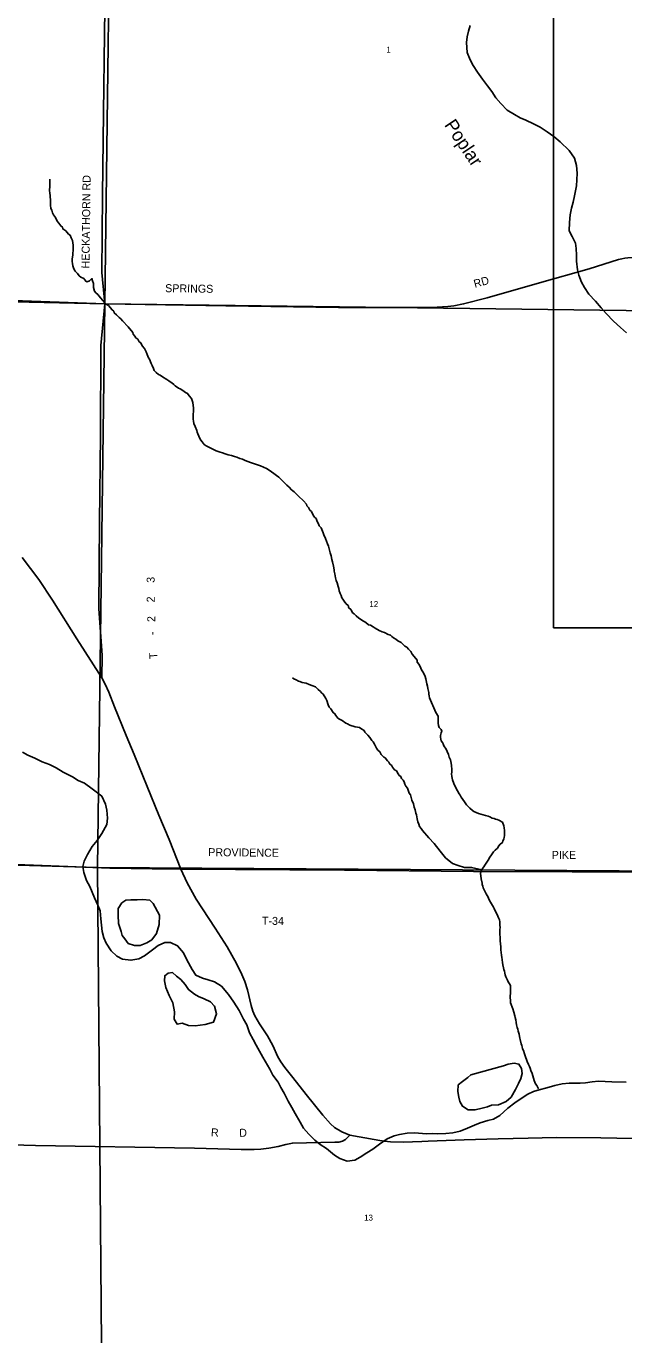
# Model space of a CAD drawing. Extents: x 1312308 to 1684953, y 460642 to 865172.
# Drawn here: x 1437978 to 1443580, y 657978 to 670241 of the extents above; entities that cross this region are included whole.
import ezdxf

# ---------------------------------------------------------------- set-up
doc = ezdxf.new("R2010")
doc.units = 0
for name, color, linetype in [('GM_X_County_Road', 7, 'Continuous'), ('GM_X_County_Road_Text', 7, 'Continuous'), ('GM_X_Minor_Lake', 7, 'Continuous'), ('GM_X_Minor_River', 7, 'Continuous'), ('GM_X_Minor_River_Text', 7, 'Continuous'), ('GM_X_Section', 7, 'Continuous'), ('GM_X_Section_Text', 7, 'Continuous'), ('GM_X_Township_Road', 7, 'Continuous'), ('GM_X_Township_Road_Text', 7, 'Continuous'), ('SH_Data', 7, 'Continuous')]:
    doc.layers.add(name, color=color, linetype=linetype)

msp = doc.modelspace()

# ---------------------------------------------------------------- linework, layer by layer
at = {"layer": 'GM_X_County_Road'}
for points in [[(1436235, 667699), (1437294, 667672), (1438715, 667638), (1439848, 667622), (1440906, 667606), (1441732, 667606), (1441830, 667608), (1441930, 667615), (1441987, 667622), (1442078, 667638), (1442298, 667695), (1442788, 667837), (1443254, 667967), (1443529, 668054), (1443561, 668061), (1443588, 668067), (1443617, 668070), (1444097, 668076)], [(1437941, 665263), (1438098, 665055), (1438226, 664863), (1438453, 664500), (1438688, 664134), (1438718, 664077), (1438753, 664001), (1438805, 663862), (1438914, 663594), (1438991, 663417), (1439111, 663118), (1439221, 662847), (1439318, 662619), (1439428, 662343), (1439486, 662214), (1439571, 662061), (1439748, 661789), (1439863, 661615), (1439949, 661458), (1440000, 661354), (1440026, 661290), (1440052, 661211), (1440086, 661063), (1440102, 661012), (1440122, 660968), (1440164, 660894), (1440240, 660779), (1440289, 660690), (1440338, 660584), (1440364, 660538), (1440401, 660484), (1440476, 660391), (1440603, 660231), (1440759, 660037), (1440831, 659955), (1440869, 659922), (1440936, 659882), (1441011, 659850), (1441100, 659834), (1441293, 659800), (1441338, 659793), (1441393, 659787), (1441510, 659784), (1441686, 659790), (1441745, 659793), (1442084, 659805), (1442401, 659816), (1442684, 659822), (1442945, 659827), (1443364, 659823), (1443962, 659813)], [(1428093, 662563), (1428093, 662563), (1436008, 662458), (1438209, 662374), (1438762, 662352), (1439160, 662345), (1439428, 662343)]]:
    msp.add_lwpolyline(points, dxfattribs=at)
at = {"layer": 'GM_X_Minor_Lake'}
for points in [[(1439169, 662020), (1439136, 662053), (1439070, 662058), (1439019, 662055), (1438959, 662055), (1438911, 662050), (1438876, 662026), (1438841, 661973), (1438839, 661911), (1438844, 661832), (1438868, 661759), (1438879, 661719)], [(1438879, 661719), (1438903, 661690), (1438934, 661645), (1438992, 661628), (1439046, 661627), (1439109, 661652), (1439156, 661681), (1439199, 661740), (1439223, 661824), (1439227, 661910), (1439169, 662020)], [(1439349, 661373), (1439309, 661366), (1439276, 661343), (1439273, 661295), (1439286, 661234), (1439319, 661157), (1439353, 661090), (1439369, 661005), (1439366, 660935), (1439393, 660890), (1439441, 660899), (1439499, 660876), (1439563, 660875), (1439654, 660885), (1439733, 660907), (1439762, 660987), (1439742, 661057), (1439705, 661100), (1439645, 661126), (1439593, 661149), (1439556, 661172)], [(1439556, 661172), (1439498, 661213), (1439469, 661262), (1439428, 661307), (1439387, 661338), (1439349, 661373)], [(1442340, 660131), (1442406, 660134), (1442477, 660165), (1442524, 660206), (1442565, 660278), (1442592, 660335), (1442615, 660381), (1442626, 660427), (1442621, 660473), (1442596, 660516), (1442552, 660523), (1442496, 660516), (1442451, 660499), (1442145, 660414)], [(1442145, 660414), (1442118, 660391), (1442104, 660379), (1442067, 660351), (1442027, 660320), (1442023, 660260), (1442034, 660205), (1442044, 660165), (1442069, 660120), (1442122, 660087), (1442186, 660088), (1442253, 660103), (1442303, 660116), (1442340, 660131)]]:
    msp.add_lwpolyline(points, dxfattribs=at)
at = {"layer": 'GM_X_Minor_River'}
for points in [[(1443606, 667367), (1443549, 667419), (1443484, 667478), (1443413, 667550), (1443368, 667601), (1443313, 667663), (1443253, 667730), (1443212, 667793), (1443183, 667844), (1443158, 667907), (1443145, 667958), (1443136, 668038), (1443136, 668095), (1443133, 668159), (1443126, 668209), (1443095, 668270), (1443066, 668323), (1443070, 668402), (1443077, 668472), (1443090, 668536), (1443104, 668592), (1443117, 668652), (1443135, 668744), (1443140, 668800), (1443141, 668863), (1443137, 668935), (1443116, 669006), (1443069, 669077), (1442983, 669159), (1442924, 669207), (1442860, 669252), (1442797, 669294), (1442733, 669325), (1442660, 669361), (1442608, 669384), (1442555, 669413), (1442487, 669454), (1442427, 669518), (1442379, 669571), (1442343, 669628), (1442302, 669683), (1442255, 669744), (1442208, 669810), (1442169, 669873), (1442138, 669926), (1442111, 669994), (1442105, 670087), (1442110, 670143), (1442123, 670195), (1442139, 670249)], [(1438426, 667966), (1438415, 667997), (1438412, 668017), (1438410, 668037), (1438409, 668059), (1438411, 668079), (1438414, 668095), (1438416, 668109), (1438419, 668145), (1438417, 668171), (1438418, 668189), (1438413, 668232), (1438400, 668258), (1438390, 668282), (1438376, 668291), (1438349, 668324), (1438321, 668342), (1438318, 668359), (1438302, 668369), (1438285, 668395), (1438269, 668414), (1438252, 668448), (1438233, 668473), (1438223, 668493), (1438218, 668518), (1438210, 668534), (1438207, 668564), (1438205, 668582), (1438206, 668604), (1438203, 668652), (1438198, 668679), (1438196, 668699), (1438196, 668715), (1438199, 668729), (1438199, 668745), (1438198, 668769), (1438199, 668807)], [(1440201, 666110), (1440173, 666122), (1440110, 666144), (1440082, 666153), (1440054, 666163), (1440030, 666172), (1440007, 666183), (1439981, 666191), (1439953, 666202), (1439929, 666209), (1439901, 666217), (1439871, 666226), (1439844, 666235), (1439818, 666244), (1439796, 666250), (1439778, 666255), (1439758, 666261), (1439715, 666284), (1439689, 666297), (1439665, 666310), (1439647, 666322), (1439626, 666345), (1439616, 666361), (1439607, 666379), (1439588, 666420), (1439580, 666438), (1439579, 666452), (1439562, 666491), (1439548, 666519), (1439547, 666541), (1439543, 666560), (1439544, 666598), (1439547, 666636), (1439547, 666650), (1439546, 666666), (1439544, 666686), (1439541, 666714), (1439528, 666751), (1439507, 666777), (1439491, 666800), (1439471, 666808), (1439446, 666827), (1439422, 666842), (1439406, 666850), (1439375, 666871), (1439361, 666883), (1439343, 666898), (1439327, 666908), (1439314, 666917), (1439296, 666929), (1439255, 666954), (1439233, 666971), (1439217, 666977), (1439197, 666996), (1439176, 667016), (1439170, 667035), (1439159, 667063), (1439149, 667079), (1439134, 667120), (1439125, 667134), (1439119, 667148), (1439112, 667165), (1439104, 667189), (1439087, 667221), (1439065, 667246), (1439052, 667274), (1439036, 667285), (1439025, 667307), (1439007, 667320), (1438996, 667338), (1438982, 667356), (1438976, 667371), (1438934, 667424), (1438881, 667479), (1438865, 667500), (1438848, 667510), (1438824, 667535), (1438803, 667554), (1438799, 667570), (1438783, 667582), (1438748, 667623), (1438721, 667638), (1438711, 667652), (1438695, 667671), (1438674, 667695), (1438649, 667726), (1438631, 667743), (1438619, 667757), (1438610, 667793), (1438609, 667831), (1438600, 667856), (1438594, 667876), (1438570, 667854), (1438550, 667845), (1438536, 667851), (1438518, 667876), (1438491, 667889), (1438475, 667903), (1438459, 667923), (1438438, 667946), (1438426, 667966)], [(1441819, 663810), (1441758, 663949), (1441756, 663965), (1441753, 663983), (1441751, 663997), (1441744, 664035), (1441738, 664057), (1441733, 664078), (1441724, 664126), (1441719, 664148), (1441700, 664189), (1441686, 664205), (1441676, 664224), (1441661, 664260), (1441644, 664283), (1441642, 664299), (1441615, 664336), (1441596, 664358), (1441582, 664383), (1441563, 664403), (1441547, 664422), (1441527, 664432), (1441514, 664444), (1441492, 664467), (1441463, 664482), (1441443, 664498), (1441421, 664511), (1441405, 664523), (1441392, 664534), (1441372, 664542), (1441338, 664559), (1441314, 664566), (1441287, 664579), (1441249, 664600), (1441229, 664614), (1441206, 664627), (1441188, 664633), (1441162, 664652), (1441147, 664664), (1441133, 664669), (1441113, 664685), (1441095, 664694), (1441070, 664715), (1441052, 664735), (1441038, 664745), (1441025, 664772), (1441000, 664793), (1440998, 664809), (1440975, 664833), (1440957, 664854), (1440947, 664872), (1440938, 664886), (1440930, 664907), (1440921, 664925), (1440913, 664951), (1440910, 664973), (1440902, 664990), (1440893, 665026), (1440884, 665046), (1440878, 665073), (1440871, 665111), (1440866, 665133), (1440866, 665147), (1440859, 665182), (1440850, 665222), (1440843, 665244), (1440837, 665277), (1440826, 665305), (1440812, 665370), (1440802, 665390), (1440785, 665440), (1440768, 665475), (1440761, 665493), (1440742, 665540), (1440724, 665560), (1440717, 665579), (1440705, 665599), (1440696, 665627), (1440680, 665642), (1440669, 665660), (1440653, 665693), (1440636, 665707), (1440624, 665732), (1440607, 665748), (1440605, 665762), (1440576, 665793), (1440531, 665836), (1440511, 665857), (1440490, 665878), (1440466, 665898), (1440443, 665921), (1440421, 665941), (1440402, 665960), (1440384, 665977), (1440345, 666014), (1440323, 666030), (1440300, 666049), (1440278, 666065), (1440254, 666080), (1440229, 666095), (1440201, 666110)], [(1441679, 662724), (1441666, 662742), (1441658, 662763), (1441649, 662787), (1441644, 662815), (1441636, 662851), (1441629, 662868), (1441624, 662898), (1441614, 662922), (1441607, 662953), (1441592, 662989), (1441581, 663037), (1441569, 663054), (1441553, 663100), (1441537, 663119), (1441527, 663137), (1441520, 663159), (1441510, 663176), (1441497, 663190), (1441489, 663210), (1441475, 663221), (1441464, 663235), (1441448, 663264), (1441431, 663274), (1441413, 663299), (1441402, 663317), (1441388, 663327), (1441378, 663344), (1441365, 663356), (1441343, 663385), (1441329, 663393), (1441306, 663418), (1441293, 663442), (1441275, 663457), (1441261, 663475), (1441242, 663514), (1441231, 663536), (1441217, 663548), (1441198, 663577), (1441180, 663597), (1441151, 663626), (1441147, 663640), (1441124, 663655), (1441102, 663668), (1441084, 663672), (1441060, 663677), (1441012, 663690), (1440989, 663703), (1440975, 663711), (1440939, 663736), (1440914, 663747), (1440898, 663757), (1440880, 663782), (1440871, 663798), (1440855, 663810), (1440834, 663845), (1440818, 663861), (1440809, 663882), (1440796, 663922), (1440786, 663940), (1440763, 663981), (1440747, 663994), (1440736, 664008), (1440716, 664026), (1440691, 664051), (1440655, 664062), (1440631, 664071), (1440601, 664086), (1440564, 664092), (1440544, 664099), (1440530, 664103), (1440508, 664116), (1440488, 664126), (1440475, 664135)], [(1441819, 663810), (1441841, 663777), (1441841, 663763), (1441839, 663745), (1441838, 663711), (1441844, 663687), (1441849, 663671), (1441867, 663652), (1441875, 663636), (1441868, 663618), (1441862, 663594), (1441862, 663580), (1441865, 663560), (1441869, 663546), (1441879, 663529), (1441887, 663515), (1441894, 663497), (1441916, 663466), (1441925, 663446), (1441937, 663418), (1441944, 663393), (1441954, 663365), (1441958, 663351), (1441961, 663335), (1441965, 663313), (1441968, 663276), (1441968, 663250), (1441966, 663236), (1441967, 663210), (1441974, 663180), (1441986, 663145), (1441992, 663129), (1442001, 663113), (1442007, 663099), (1442021, 663076), (1442036, 663048), (1442046, 663034), (1442056, 663016), (1442085, 662973), (1442104, 662946), (1442118, 662932), (1442136, 662912), (1442160, 662893), (1442175, 662883), (1442197, 662872), (1442219, 662864), (1442239, 662857), (1442283, 662845), (1442307, 662838), (1442323, 662832), (1442347, 662821), (1442363, 662817), (1442378, 662811), (1442394, 662806), (1442408, 662800), (1442444, 662781), (1442455, 662749), (1442459, 662729), (1442461, 662703), (1442460, 662655), (1442457, 662641), (1442455, 662624), (1442447, 662607), (1442441, 662591), (1442422, 662577), (1442408, 662561), (1442395, 662539), (1442375, 662521), (1442359, 662504), (1442338, 662476), (1442324, 662454), (1442307, 662426), (1442295, 662406), (1442278, 662378), (1442268, 662365), (1442256, 662349), (1442249, 662335), (1442241, 662317), (1442237, 662301), (1442238, 662281), (1442244, 662250), (1442251, 662212), (1442253, 662198), (1442257, 662184), (1442262, 662168), (1442276, 662137), (1442289, 662111), (1442299, 662095), (1442307, 662078), (1442316, 662062), (1442330, 662034), (1442349, 662001), (1442357, 661987), (1442365, 661973), (1442378, 661945), (1442392, 661918), (1442400, 661902), (1442405, 661886), (1442413, 661866), (1442417, 661849), (1442418, 661827)], [(1441731, 659862), (1441617, 659872), (1441548, 659868), (1441478, 659857), (1441427, 659842), (1441360, 659814), (1441289, 659765), (1441228, 659718), (1441171, 659683), (1441108, 659644), (1441057, 659615), (1440986, 659605), (1440919, 659631), (1440867, 659662), (1440794, 659724), (1440735, 659763), (1440684, 659804), (1440627, 659858), (1440578, 659915), (1440545, 659972), (1440498, 660053), (1440468, 660110), (1440435, 660167), (1440396, 660244), (1440365, 660295), (1440340, 660346), (1440290, 660413), (1440261, 660468), (1440197, 660580), (1440166, 660637), (1440135, 660692), (1440106, 660746), (1440072, 660809), (1440045, 660882), (1440014, 660937), (1439974, 661018), (1439923, 661096), (1439873, 661169), (1439810, 661245), (1439743, 661286), (1439683, 661304), (1439631, 661319), (1439568, 661350), (1439533, 661401), (1439483, 661491), (1439452, 661558), (1439397, 661625), (1439332, 661655), (1439279, 661654), (1439215, 661627), (1439161, 661586), (1439088, 661530), (1439033, 661501), (1438959, 661488), (1438881, 661500), (1438827, 661527), (1438776, 661577), (1438729, 661648), (1438706, 661699), (1438690, 661759), (1438685, 661816), (1438678, 661876), (1438670, 661950), (1438649, 662005), (1438618, 662074), (1438597, 662125), (1438574, 662178), (1438544, 662236), (1438519, 662311), (1438510, 662366), (1438520, 662418), (1438553, 662479), (1438597, 662555), (1438642, 662612), (1438686, 662675), (1438734, 662759), (1438741, 662821), (1438735, 662895), (1438720, 662950), (1438686, 663025), (1438595, 663095), (1438524, 663149), (1438466, 663174), (1438411, 663206), (1438325, 663252), (1438260, 663293), (1438195, 663323), (1438129, 663349), (1438059, 663382), (1437994, 663410), (1437942, 663437)], [(1441679, 662724), (1441694, 662705), (1441753, 662635), (1441802, 662584), (1441857, 662512), (1441909, 662449), (1441973, 662396), (1442028, 662376), (1442086, 662359), (1442152, 662358), (1442249, 662335)], [(1442418, 661827), (1442418, 661813), (1442420, 661797), (1442417, 661775), (1442419, 661743), (1442418, 661729), (1442420, 661705), (1442420, 661687), (1442421, 661666), (1442423, 661646), (1442426, 661610), (1442428, 661582), (1442429, 661564), (1442433, 661532), (1442435, 661518), (1442438, 661491), (1442442, 661467), (1442447, 661447), (1442453, 661417), (1442456, 661401), (1442460, 661387), (1442464, 661368), (1442468, 661352), (1442473, 661334), (1442479, 661320), (1442489, 661302), (1442500, 661279), (1442510, 661265), (1442518, 661249), (1442519, 661231), (1442519, 661193), (1442516, 661173), (1442514, 661157), (1442514, 661138), (1442517, 661112), (1442519, 661090), (1442523, 661074), (1442532, 661050), (1442540, 661032), (1442549, 661003), (1442559, 660967), (1442562, 660951), (1442566, 660931), (1442570, 660906), (1442575, 660884), (1442581, 660858), (1442586, 660842), (1442590, 660824), (1442598, 660795), (1442601, 660775), (1442605, 660759), (1442609, 660745), (1442618, 660705), (1442624, 660691), (1442627, 660676), (1442631, 660658), (1442639, 660642), (1442648, 660610), (1442656, 660592), (1442662, 660575), (1442667, 660557), (1442675, 660541), (1442686, 660513), (1442696, 660492), (1442702, 660478), (1442709, 660454), (1442721, 660426), (1442727, 660406), (1442732, 660383), (1442740, 660361), (1442745, 660345), (1442751, 660331), (1442763, 660314), (1442773, 660296), (1442780, 660282)], [(1443467, 660348), (1443343, 660355), (1443283, 660350), (1443220, 660341), (1443170, 660336), (1443118, 660337), (1443068, 660338), (1443003, 660329), (1442933, 660315), (1442858, 660294), (1442786, 660273), (1442733, 660258), (1442681, 660233), (1442626, 660200), (1442557, 660153), (1442491, 660102), (1442418, 660033), (1442357, 659998), (1442305, 659987), (1442234, 659964), (1442181, 659943), (1442113, 659915), (1442046, 659886), (1441977, 659871), (1441911, 659864), (1441837, 659862), (1441783, 659865), (1441731, 659862)], [(1443603, 660346), (1443467, 660348)]]:
    msp.add_lwpolyline(points, dxfattribs=at)
at = {"layer": 'GM_X_Section'}
for points in [[(1438782, 672734), (1438715, 667639), (1433391, 667833), (1433385, 672746), (1438508, 672731)], [(1438782, 672734), (1444176, 672688), (1444097, 667788), (1444089, 667570), (1438715, 667639)], [(1438715, 667639), (1438647, 662357), (1433331, 662515), (1433391, 667833)], [(1444089, 667570), (1444023, 662466), (1444022, 662322), (1438647, 662357), (1438715, 667639)], [(1438647, 662357), (1438689, 657144), (1433314, 657259), (1433331, 662515)], [(1438647, 662357), (1444022, 662322), (1443918, 657174), (1443914, 657078), (1438689, 657144)]]:
    msp.add_lwpolyline(points, close=True, dxfattribs=at)
at = {"layer": 'GM_X_Township_Road'}
for points in [[(1438688, 664134), (1438689, 664345), (1438659, 664786), (1438666, 665594), (1438676, 666405), (1438679, 667249), (1438715, 667638), (1438686, 667932), (1438694, 668657), (1438702, 669429), (1438712, 670168), (1438721, 670880), (1438732, 671246)], [(1439428, 662343), (1440963, 662332), (1442170, 662320), (1444017, 662315)], [(1436005, 659812), (1438066, 659754), (1439557, 659727), (1439994, 659716), (1440114, 659716), (1440177, 659717), (1440253, 659728), (1440339, 659743), (1440413, 659763), (1440474, 659775), (1440870, 659783), (1440910, 659784), (1440942, 659793), (1440971, 659810), (1441011, 659850)]]:
    msp.add_lwpolyline(points, dxfattribs=at)
at = {"layer": 'SH_Data'}
for p, q in [((1442922, 682555), (1442922, 664603)), ((1442922, 664603), (1460874, 664603))]:
    msp.add_line(p, q, dxfattribs=at)

# ---------------------------------------------------------------- texts
at = {"layer": 'GM_X_County_Road_Text'}
for s, rotation, p in [('RD', 15.5498, (1442184, 667789)), ('SPRINGS', 359.1883, (1439280, 667749))]:
    msp.add_text(s, height=75, rotation=rotation, dxfattribs=at).set_placement(p)
at = {"layer": 'GM_X_Minor_River_Text'}
msp.add_text('Poplar ', height=125.1, rotation=303.7763, dxfattribs=at).set_placement((1441893, 669316))
at = {"layer": 'GM_X_Section_Text'}
for s, p in [('1', (1441355, 669994)), ('12', (1441195, 664799)), ('13', (1441146, 659049))]:
    msp.add_text(s, height=55.3, rotation=0, dxfattribs=at).set_placement(p)
at = {"layer": 'GM_X_Township_Road_Text'}
for s, rotation, p in [('HECKATHORN RD', 89.2734, (1438571, 667971)), ('3', 89.5056, (1439182, 665025)), ('2', 90.497, (1439183, 664842)), ('2', 91.8374, (1439189, 664659)), ('-', 92.9404, (1439195, 664537)), ('T', 93.4264, (1439209, 664314)), ('PROVIDENCE', 359.4577, (1439684, 662464)), ('PIKE', 0, (1442904, 662438)), ('T-34', 359.2931, (1440187, 661821)), ('R', 358.7627, (1439709, 659838)), ('D', 2.3602, (1439976, 659833))]:
    msp.add_text(s, height=75, rotation=rotation, dxfattribs=at).set_placement(p)

doc.saveas('drawing.dxf')
